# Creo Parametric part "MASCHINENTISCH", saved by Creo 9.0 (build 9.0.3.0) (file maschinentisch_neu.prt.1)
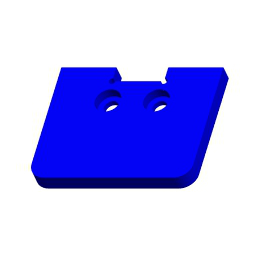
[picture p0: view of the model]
Units: millimeter Kilogram Sec (mmKs); MM, KILOGRAM, SECS
Materials in the file: STAHL

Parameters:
  SCHRAUBEN_GROESSE = "M4x.7"
  METRISCH = "JA"
  WERKSTOFF = "Stahl"
  ERSTELLER = "ARINDA"
  BENENNUNG = "XXX"
  TEILETYP = "K"
  PTC_MASTER_MATERIAL = "STAHL"

Other parameters: ANSENKDURCHMESSER, ANSENKTIEFE, BOHR_DURCHM, MASSE

Created from: ARINDA_STARTTEIL.PRT

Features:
  1. coordinate system
  2. datum plane "RECHTS_Y-Z"
  3. datum plane "OBEN_X-Z"
  4. datum plane "VORNE_X-Y"
  5. datum axis
  6. datum axis
  7. datum axis
  8. datum point "PNT0"
  9. extrusion "Profil 1"
  10. extruded cut "Profil 2"
  11. extruded cut "Profil 3"
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
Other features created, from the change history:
  coordinate system "CS1"
  sketch "Skizze 1"
  hole "Bohrung 1"
  pattern "Muster 1"
  hole "Bohrung 1 [8]"
  round "Rundung 1"

Other named items: MASCHINENTISCH, NUT, FREIMACHUNG, BEFESTIGUNG, A_X, A_Y, A_Z, CS0

Layers: 01_ACHSEN, 01_ACHSEN_STD, 01_EBENEN_STD, 01_KOORDSYS_STD, 01_KURVEN, 01_PUNKTE_STD, VOLUMENGEOMETRIE

Notes: M4x.7 | LÖSCHEN |  BOHREN (  | 4.500 | DURCH |   -(  |  ) BOHRUNG

Surfaces: 11 plane, 10 cylinder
